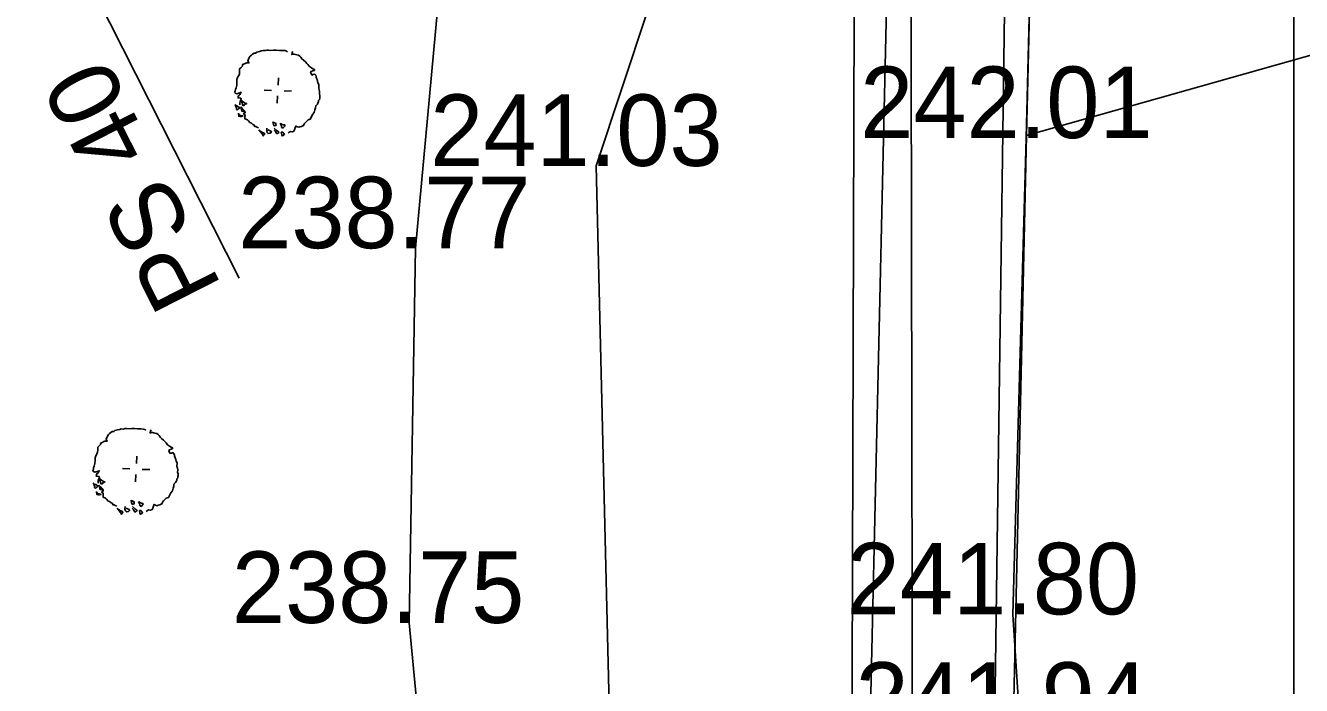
# Model space of a CAD drawing. Extents: x -601754 to -601440, y -1201912 to -1200862.
# Drawn here: x -601534.51 to -601498.82, y -1201609.03 to -1201590.57 of the extents above; entities that cross this region are included whole.
import ezdxf

# ---------------------------------------------------------------- set-up
doc = ezdxf.new("R2010")
doc.units = 0
for name, color, linetype in [('Hranice parcel', 7, 'Continuous'), ('u_hrany', 7, 'Continuous'), ('u_popis', 7, 'Continuous'), ('u_pricne_cesta', 7, 'Continuous'), ('u_vysadba', 7, 'Continuous'), ('u_vyska', 7, 'Continuous')]:
    doc.layers.add(name, color=color, linetype=linetype)

msp = doc.modelspace()

# ---------------------------------------------------------------- linework, layer by layer
at = {"layer": 'Hranice parcel'}
for p, q in [((-601506.51, -1201593.65), (-601506.34, -1201586.43)), ((-601506.89, -1201610.28), (-601506.51, -1201593.65))]:
    msp.add_line(p, q, dxfattribs=at)
for points in [[(-601518.5, -1201574.62), (-601510.22, -1201581.07), (-601510.94, -1201612.53), (-601510.72, -1201619.53), (-601510.05, -1201624.75), (-601508.24, -1201633.75), (-601505.86, -1201640.82), (-601502.47, -1201648.58), (-601498.5, -1201656.04), (-601493.62, -1201663.46), (-601488.75, -1201670.45), (-601479.72, -1201682.69), (-601461.88, -1201705.09), (-601454.585, -1201713.629)], [(-601454.585, -1201578.974), (-601506.51, -1201593.65)]]:
    msp.add_lwpolyline(points, dxfattribs=at)
at = {"layer": 'u_hrany'}
for points in [[(-601512.26, -1201390.52), (-601510.47, -1201401.41), (-601510.09, -1201413.72), (-601511.79, -1201441.97), (-601511.82, -1201455.52), (-601508.66, -1201487.01), (-601505.94, -1201512.07), (-601505.14, -1201523.95), (-601505.37, -1201547.09), (-601506.1, -1201561.67), (-601507, -1201580.71), (-601507.44, -1201612.51), (-601506.59, -1201624.18), (-601504.84, -1201632.93)], [(-601506.52, -1201593.72), (-601505.37, -1201547.09)], [(-601514.2, -1201569.51), (-601517.03, -1201570.93), (-601522.49, -1201584.67), (-601523.6, -1201596.8), (-601523.78, -1201607.28), (-601522.35, -1201622.38), (-601520.26, -1201632.29), (-601514.11, -1201648.21), (-601507.05, -1201660.77), (-601502.96, -1201664.86), (-601510.13, -1201648.82), (-601514.08, -1201638.6), (-601517, -1201627.14), (-601517.98, -1201618.06), (-601518.55, -1201594.5), (-601514.93, -1201583.59), (-601509.76, -1201580.82)], [(-601507.17, -1201633.88), (-601509.44, -1201619.72), (-601509.7, -1201612.19), (-601509.76, -1201580.82), (-601509.75, -1201574.25)], [(-601514.93, -1201583.59), (-601511.33, -1201590.16), (-601511.4, -1201611.89), (-601510.42, -1201625.27), (-601508.49, -1201633.89)], [(-601500.93, -1201614.59), (-601506.68, -1201610.38), (-601506.9, -1201607.04), (-601506.52, -1201593.72)]]:
    msp.add_lwpolyline(points, dxfattribs=at)
at = {"layer": 'u_popis'}
msp.add_lwpolyline([(-601499.032, -1201585.54), (-601499.032, -1201622.028), (-601499.032, -1201605.689)], dxfattribs=at)
at = {"layer": 'u_pricne_cesta'}
msp.add_lwpolyline([(-601528.534, -1201597.635), (-601537.585, -1201579.8), (-601546.635, -1201561.965)], dxfattribs=at)
at = {"layer": 'u_vysadba'}
for points in [[(-601528.445, -1201591.696), (-601528.444, -1201591.667), (-601528.384, -1201591.641), (-601528.354, -1201591.628), (-601528.324, -1201591.615), (-601528.295, -1201591.616), (-601528.266, -1201591.618), (-601528.279, -1201591.588), (-601528.292, -1201591.558), (-601528.275, -1201591.515), (-601528.258, -1201591.472), (-601528.226, -1201591.43), (-601528.196, -1201591.402), (-601528.165, -1201591.374), (-601528.12, -1201591.347), (-601528.076, -1201591.35), (-601528.045, -1201591.322), (-601527.97, -1201591.297), (-601527.911, -1201591.285), (-601527.867, -1201591.273), (-601527.808, -1201591.276), (-601527.764, -1201591.264), (-601527.72, -1201591.266), (-601527.647, -1201591.27), (-601527.573, -1201591.259), (-601527.5, -1201591.263), (-601527.412, -1201591.268), (-601527.325, -1201591.272), (-601527.252, -1201591.276), (-601527.209, -1201591.293), (-601527.18, -1201591.309)], [(-601527.034, -1201591.302), (-601527.05, -1201591.331), (-601527.051, -1201591.36), (-601527.067, -1201591.388), (-601527.023, -1201591.376), (-601526.994, -1201591.378), (-601526.964, -1201591.379), (-601526.921, -1201591.396), (-601526.878, -1201591.398), (-601526.835, -1201591.43), (-601526.808, -1201591.461), (-601526.781, -1201591.506), (-601526.739, -1201591.538), (-601526.682, -1201591.584), (-601526.641, -1201591.631), (-601526.613, -1201591.661), (-601526.573, -1201591.722), (-601526.516, -1201591.754), (-601526.473, -1201591.786), (-601526.43, -1201591.803), (-601526.432, -1201591.832)], [(-601528.445, -1201591.696), (-601528.446, -1201591.711), (-601528.492, -1201591.752), (-601528.523, -1201591.78), (-601528.525, -1201591.824), (-601528.528, -1201591.868), (-601528.531, -1201591.926), (-601528.548, -1201591.969), (-601528.564, -1201591.998), (-601528.58, -1201592.026), (-601528.598, -1201592.084), (-601528.599, -1201592.113), (-601528.602, -1201592.171), (-601528.605, -1201592.215), (-601528.606, -1201592.244), (-601528.625, -1201592.316), (-601528.642, -1201592.36), (-601528.644, -1201592.403), (-601528.66, -1201592.432), (-601528.647, -1201592.462), (-601528.604, -1201592.479), (-601528.515, -1201592.454), (-601528.485, -1201592.441), (-601528.517, -1201592.498), (-601528.548, -1201592.526), (-601528.564, -1201592.554), (-601528.566, -1201592.598), (-601528.537, -1201592.599), (-601528.493, -1201592.602), (-601528.48, -1201592.632), (-601528.497, -1201592.675), (-601528.513, -1201592.703), (-601528.516, -1201592.747), (-601528.518, -1201592.791)], [(-601526.432, -1201591.832), (-601526.477, -1201591.844), (-601526.521, -1201591.857), (-601526.537, -1201591.885), (-601526.524, -1201591.915), (-601526.497, -1201591.96), (-601526.467, -1201591.947), (-601526.423, -1201591.935), (-601526.395, -1201591.966), (-601526.382, -1201591.996), (-601526.384, -1201592.025), (-601526.357, -1201592.085), (-601526.345, -1201592.129), (-601526.333, -1201592.174), (-601526.306, -1201592.219), (-601526.308, -1201592.249), (-601526.31, -1201592.292), (-601526.311, -1201592.322), (-601526.299, -1201592.366), (-601526.288, -1201592.425), (-601526.291, -1201592.484), (-601526.279, -1201592.543), (-601526.281, -1201592.572), (-601526.282, -1201592.601), (-601526.285, -1201592.645), (-601526.315, -1201592.673), (-601526.317, -1201592.702), (-601526.334, -1201592.745), (-601526.35, -1201592.773), (-601526.396, -1201592.815), (-601526.399, -1201592.873), (-601526.417, -1201592.931), (-601526.435, -1201593.003), (-601526.482, -1201593.059), (-601526.515, -1201593.131), (-601526.548, -1201593.188), (-601526.607, -1201593.214), (-601526.638, -1201593.241), (-601526.684, -1201593.283), (-601526.716, -1201593.325), (-601526.733, -1201593.368), (-601526.793, -1201593.394), (-601526.837, -1201593.407), (-601526.867, -1201593.42), (-601526.91, -1201593.403), (-601526.953, -1201593.386), (-601526.97, -1201593.429), (-601526.988, -1201593.487), (-601527.005, -1201593.53), (-601527.049, -1201593.542), (-601527.093, -1201593.54)], [(-601527.446, -1201592.238), (-601527.435, -1201592.033)], [(-601527.63, -1201592.389), (-601527.834, -1201592.378)], [(-601527.462, -1201592.544), (-601527.473, -1201592.749)], [(-601527.279, -1201592.408), (-601527.074, -1201592.404)], [(-601528.649, -1201592.784), (-601528.636, -1201592.814), (-601528.624, -1201592.858), (-601528.611, -1201592.888), (-601528.612, -1201592.917), (-601528.584, -1201592.934), (-601528.553, -1201592.906), (-601528.507, -1201592.864), (-601528.536, -1201592.863), (-601528.579, -1201592.831), (-601528.622, -1201592.814)], [(-601528.492, -1201592.851), (-601528.45, -1201592.897), (-601528.409, -1201592.943), (-601528.367, -1201592.974)], [(-601528.367, -1201592.974), (-601528.396, -1201592.973), (-601528.425, -1201592.971), (-601528.454, -1201592.97), (-601528.467, -1201592.94), (-601528.466, -1201592.911), (-601528.479, -1201592.881)], [(-601528.467, -1201592.662), (-601528.469, -1201592.705), (-601528.456, -1201592.735), (-601528.444, -1201592.78), (-601528.431, -1201592.81), (-601528.402, -1201592.811), (-601528.386, -1201592.783), (-601528.326, -1201592.757), (-601528.369, -1201592.74), (-601528.397, -1201592.724), (-601528.454, -1201592.692)], [(-601528.559, -1201593.023), (-601528.55, -1201593.111), (-601528.506, -1201593.113), (-601528.476, -1201593.115), (-601528.432, -1201593.103), (-601528.49, -1201593.085), (-601528.533, -1201593.083), (-601528.546, -1201593.053)], [(-601527.995, -1201593.433), (-601528.038, -1201593.416), (-601528.067, -1201593.4), (-601528.096, -1201593.399), (-601528.123, -1201593.353), (-601528.151, -1201593.337), (-601528.194, -1201593.306), (-601528.237, -1201593.289), (-601528.278, -1201593.243), (-601528.306, -1201593.212), (-601528.377, -1201593.179), (-601528.375, -1201593.135), (-601528.373, -1201593.091), (-601528.386, -1201593.061), (-601528.414, -1201593.045), (-601528.383, -1201593.003), (-601528.354, -1201593.004)], [(-601527.591, -1201593.264), (-601527.58, -1201593.338), (-601527.554, -1201593.383), (-601527.509, -1201593.371), (-601527.507, -1201593.342), (-601527.506, -1201593.313), (-601527.549, -1201593.296), (-601527.577, -1201593.28)], [(-601527.388, -1201593.304), (-601527.362, -1201593.364), (-601527.35, -1201593.409), (-601527.322, -1201593.44), (-601527.292, -1201593.427), (-601527.261, -1201593.384), (-601527.259, -1201593.355), (-601527.303, -1201593.353), (-601527.331, -1201593.337), (-601527.36, -1201593.32), (-601527.389, -1201593.319)], [(-601527.984, -1201593.492), (-601527.888, -1201593.615), (-601527.861, -1201593.66), (-601527.829, -1201593.618), (-601527.828, -1201593.589), (-601527.856, -1201593.572), (-601527.899, -1201593.555), (-601527.928, -1201593.539), (-601527.956, -1201593.523)], [(-601527.762, -1201593.446), (-601527.766, -1201593.519), (-601527.753, -1201593.563), (-601527.726, -1201593.594), (-601527.667, -1201593.582), (-601527.636, -1201593.555), (-601527.649, -1201593.525), (-601527.692, -1201593.508), (-601527.735, -1201593.491)], [(-601527.557, -1201593.442), (-601527.473, -1201593.519), (-601527.444, -1201593.536), (-601527.431, -1201593.566), (-601527.462, -1201593.593), (-601527.491, -1201593.592), (-601527.504, -1201593.562), (-601527.531, -1201593.516), (-601527.559, -1201593.486)], [(-601527.358, -1201593.555), (-601527.347, -1201593.629), (-601527.334, -1201593.659), (-601527.304, -1201593.646), (-601527.272, -1201593.603), (-601527.3, -1201593.573), (-601527.328, -1201593.556), (-601527.358, -1201593.555)], [(-601527.093, -1201593.54), (-601527.138, -1201593.552), (-601527.169, -1201593.579)], [(-601532.412, -1201602.277), (-601532.41, -1201602.248), (-601532.35, -1201602.222), (-601532.32, -1201602.209), (-601532.29, -1201602.196), (-601532.261, -1201602.197), (-601532.232, -1201602.199), (-601532.245, -1201602.169), (-601532.258, -1201602.139), (-601532.241, -1201602.096), (-601532.224, -1201602.053), (-601532.193, -1201602.011), (-601532.162, -1201601.983), (-601532.131, -1201601.955), (-601532.086, -1201601.928), (-601532.042, -1201601.931), (-601532.011, -1201601.903), (-601531.937, -1201601.878), (-601531.878, -1201601.866), (-601531.833, -1201601.854), (-601531.775, -1201601.857), (-601531.73, -1201601.845), (-601531.686, -1201601.847), (-601531.613, -1201601.851), (-601531.539, -1201601.84), (-601531.466, -1201601.844), (-601531.379, -1201601.849), (-601531.291, -1201601.853), (-601531.218, -1201601.857), (-601531.175, -1201601.874), (-601531.147, -1201601.89)], [(-601531, -1201601.883), (-601531.016, -1201601.912), (-601531.018, -1201601.941), (-601531.034, -1201601.969), (-601530.989, -1201601.957), (-601530.96, -1201601.958), (-601530.931, -1201601.96), (-601530.888, -1201601.977), (-601530.844, -1201601.979), (-601530.802, -1201602.011), (-601530.774, -1201602.042), (-601530.747, -1201602.087), (-601530.705, -1201602.118), (-601530.649, -1201602.165), (-601530.607, -1201602.211), (-601530.58, -1201602.242), (-601530.539, -1201602.303), (-601530.482, -1201602.335), (-601530.44, -1201602.367), (-601530.397, -1201602.384), (-601530.398, -1201602.413)], [(-601532.412, -1201602.277), (-601532.413, -1201602.292), (-601532.459, -1201602.333), (-601532.489, -1201602.361), (-601532.492, -1201602.405), (-601532.494, -1201602.449), (-601532.497, -1201602.507), (-601532.514, -1201602.55), (-601532.53, -1201602.578), (-601532.546, -1201602.607), (-601532.564, -1201602.664), (-601532.566, -1201602.694), (-601532.569, -1201602.752), (-601532.571, -1201602.796), (-601532.573, -1201602.825), (-601532.591, -1201602.897), (-601532.608, -1201602.94), (-601532.61, -1201602.984), (-601532.626, -1201603.013), (-601532.613, -1201603.043), (-601532.57, -1201603.059), (-601532.481, -1201603.035), (-601532.451, -1201603.022), (-601532.483, -1201603.079), (-601532.514, -1201603.106), (-601532.53, -1201603.135), (-601532.533, -1201603.179), (-601532.503, -1201603.18), (-601532.46, -1201603.182), (-601532.447, -1201603.212), (-601532.464, -1201603.255), (-601532.48, -1201603.284), (-601532.482, -1201603.328), (-601532.484, -1201603.372)], [(-601531.412, -1201602.819), (-601531.402, -1201602.614)], [(-601530.398, -1201602.413), (-601530.443, -1201602.425), (-601530.487, -1201602.437), (-601530.504, -1201602.466), (-601530.491, -1201602.496), (-601530.464, -1201602.541), (-601530.434, -1201602.528), (-601530.389, -1201602.516), (-601530.361, -1201602.547), (-601530.348, -1201602.577), (-601530.35, -1201602.606), (-601530.324, -1201602.666), (-601530.312, -1201602.71), (-601530.299, -1201602.755), (-601530.272, -1201602.8), (-601530.274, -1201602.829), (-601530.276, -1201602.873), (-601530.278, -1201602.902), (-601530.265, -1201602.947), (-601530.254, -1201603.006), (-601530.257, -1201603.065), (-601530.246, -1201603.124), (-601530.247, -1201603.153), (-601530.249, -1201603.182), (-601530.251, -1201603.226), (-601530.282, -1201603.254), (-601530.283, -1201603.283), (-601530.3, -1201603.326), (-601530.316, -1201603.354), (-601530.362, -1201603.396), (-601530.365, -1201603.454), (-601530.383, -1201603.512), (-601530.402, -1201603.584), (-601530.449, -1201603.64), (-601530.482, -1201603.712), (-601530.514, -1201603.768), (-601530.574, -1201603.795), (-601530.605, -1201603.822), (-601530.651, -1201603.864), (-601530.682, -1201603.906), (-601530.699, -1201603.949), (-601530.759, -1201603.975), (-601530.804, -1201603.987), (-601530.834, -1201604.001), (-601530.877, -1201603.984), (-601530.92, -1201603.967), (-601530.937, -1201604.01), (-601530.954, -1201604.067), (-601530.971, -1201604.11), (-601531.016, -1201604.123), (-601531.06, -1201604.12)], [(-601531.596, -1201602.97), (-601531.8, -1201602.959)], [(-601531.246, -1201602.989), (-601531.04, -1201602.985)], [(-601532.434, -1201603.242), (-601532.436, -1201603.286), (-601532.423, -1201603.316), (-601532.411, -1201603.361), (-601532.397, -1201603.391), (-601532.368, -1201603.392), (-601532.352, -1201603.364), (-601532.292, -1201603.338), (-601532.335, -1201603.321), (-601532.364, -1201603.305), (-601532.42, -1201603.272)], [(-601531.429, -1201603.125), (-601531.439, -1201603.33)], [(-601532.616, -1201603.365), (-601532.603, -1201603.395), (-601532.59, -1201603.439), (-601532.577, -1201603.469), (-601532.579, -1201603.498), (-601532.55, -1201603.514), (-601532.52, -1201603.487), (-601532.474, -1201603.445), (-601532.503, -1201603.444), (-601532.545, -1201603.412), (-601532.588, -1201603.395)], [(-601532.526, -1201603.604), (-601532.516, -1201603.692), (-601532.472, -1201603.694), (-601532.443, -1201603.696), (-601532.398, -1201603.684), (-601532.456, -1201603.666), (-601532.5, -1201603.664), (-601532.513, -1201603.634)], [(-601532.458, -1201603.431), (-601532.417, -1201603.478), (-601532.375, -1201603.524), (-601532.333, -1201603.555)], [(-601532.333, -1201603.555), (-601532.362, -1201603.554), (-601532.391, -1201603.552), (-601532.421, -1201603.551), (-601532.434, -1201603.521), (-601532.432, -1201603.491), (-601532.445, -1201603.461)], [(-601531.962, -1201604.014), (-601532.005, -1201603.997), (-601532.033, -1201603.981), (-601532.062, -1201603.98), (-601532.089, -1201603.934), (-601532.118, -1201603.918), (-601532.16, -1201603.886), (-601532.203, -1201603.87), (-601532.245, -1201603.823), (-601532.272, -1201603.793), (-601532.344, -1201603.76), (-601532.341, -1201603.716), (-601532.339, -1201603.672), (-601532.352, -1201603.642), (-601532.381, -1201603.626), (-601532.349, -1201603.584), (-601532.32, -1201603.585)], [(-601531.728, -1201604.026), (-601531.732, -1201604.099), (-601531.72, -1201604.144), (-601531.692, -1201604.175), (-601531.633, -1201604.163), (-601531.602, -1201604.136), (-601531.615, -1201604.106), (-601531.658, -1201604.089), (-601531.701, -1201604.072)], [(-601531.558, -1201603.845), (-601531.547, -1201603.919), (-601531.52, -1201603.964), (-601531.475, -1201603.952), (-601531.474, -1201603.923), (-601531.472, -1201603.894), (-601531.515, -1201603.877), (-601531.544, -1201603.86)], [(-601531.523, -1201604.023), (-601531.439, -1201604.1), (-601531.411, -1201604.116), (-601531.398, -1201604.146), (-601531.428, -1201604.174), (-601531.458, -1201604.173), (-601531.471, -1201604.143), (-601531.498, -1201604.097), (-601531.525, -1201604.066)], [(-601531.355, -1201603.885), (-601531.329, -1201603.945), (-601531.316, -1201603.99), (-601531.289, -1201604.02), (-601531.259, -1201604.007), (-601531.227, -1201603.965), (-601531.226, -1201603.936), (-601531.269, -1201603.934), (-601531.298, -1201603.917), (-601531.326, -1201603.901), (-601531.355, -1201603.9)], [(-601531.95, -1201604.073), (-601531.854, -1201604.196), (-601531.827, -1201604.241), (-601531.796, -1201604.199), (-601531.794, -1201604.169), (-601531.823, -1201604.153), (-601531.866, -1201604.136), (-601531.894, -1201604.12), (-601531.923, -1201604.104)], [(-601531.324, -1201604.136), (-601531.313, -1201604.209), (-601531.3, -1201604.239), (-601531.27, -1201604.226), (-601531.239, -1201604.184), (-601531.266, -1201604.153), (-601531.295, -1201604.137), (-601531.324, -1201604.136)], [(-601531.06, -1201604.12), (-601531.104, -1201604.133), (-601531.135, -1201604.16)]]:
    msp.add_lwpolyline(points, dxfattribs=at)

# ---------------------------------------------------------------- texts
at = {"layer": 'u_pricne_cesta'}
msp.add_text('PS 40', height=2, rotation=116.9057, dxfattribs=at).set_placement((-601529.005, -1201597.874))
at = {"layer": 'u_vyska'}
for s, p in [('242.01', (-601511.166, -1201593.72)), ('241.03', (-601523.194, -1201594.5)), ('238.77', (-601528.565, -1201596.8)), ('241.80', (-601511.544, -1201607.04)), ('238.75', (-601528.741, -1201607.28)), ('241.94', (-601511.296, -1201610.38))]:
    msp.add_text(s, height=2, dxfattribs=at).set_placement(p)

doc.saveas('drawing.dxf')
